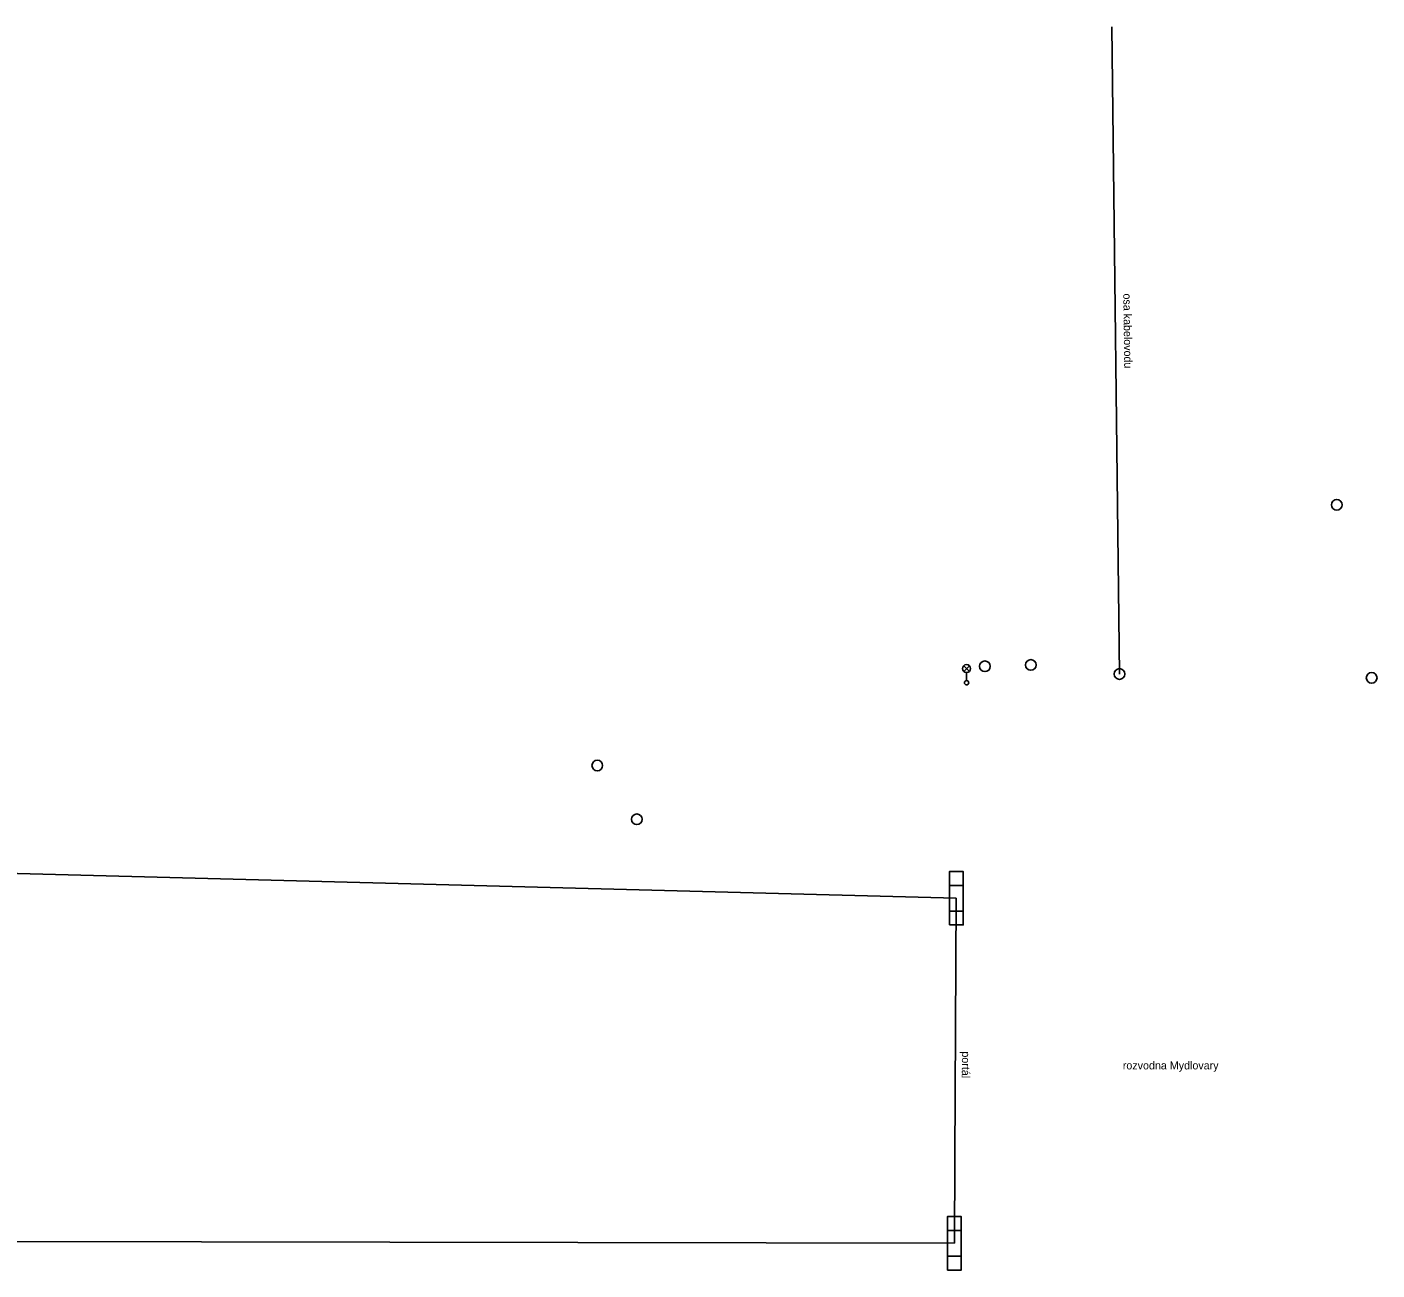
# Model space of a CAD drawing. Extents: x -763601 to -762500, y -1153000 to -1152585.
# Drawn here: x -762629.8 to -762503.3, y -1152701 to -1152584.5 of the extents above; entities that cross this region are included whole.
import ezdxf

# ---------------------------------------------------------------- set-up
doc = ezdxf.new("R2010")
doc.units = 0
for name, color, linetype in [('Vrstva 1', 7, 'Continuous'), ('Vrstva 10', 7, 'Continuous'), ('Vrstva 11', 7, 'Continuous'), ('Vrstva 2', 7, 'Continuous'), ('Vrstva 9', 7, 'Continuous')]:
    doc.layers.add(name, color=color, linetype=linetype)

msp = doc.modelspace()

# ---------------------------------------------------------------- linework, layer by layer
at = {"layer": 'Vrstva 1'}
for p, q in [((-762543.33, -1152667.4), (-762543.33, -1152665)), ((-762542.03, -1152667.4), (-762542.03, -1152665)), ((-762543.51, -1152699.74), (-762543.51, -1152697.34)), ((-762542.21, -1152699.74), (-762542.21, -1152697.34))]:
    msp.add_line(p, q, dxfattribs=at)
for points in [[(-762820.27, -1152623.02), (-762631.83, -1152663.84), (-762542.68, -1152666.2)], [(-762542.86, -1152698.54), (-762542.83, -1152690.55), (-762542.68, -1152666.2)], [(-762631.06, -1152698.36), (-762542.86, -1152698.54)]]:
    msp.add_lwpolyline(points, dxfattribs=at)
for points in [[(-762543.33, -1152665), (-762542.03, -1152665), (-762542.03, -1152663.7), (-762543.33, -1152663.7)], [(-762543.33, -1152668.7), (-762542.03, -1152668.7), (-762542.03, -1152667.4), (-762543.33, -1152667.4)], [(-762543.51, -1152697.34), (-762542.21, -1152697.34), (-762542.21, -1152696.04), (-762543.51, -1152696.04)], [(-762543.51, -1152701.04), (-762542.21, -1152701.04), (-762542.21, -1152699.74), (-762543.51, -1152699.74)]]:
    msp.add_lwpolyline(points, close=True, dxfattribs=at)
at = {"layer": 'Vrstva 11'}
msp.add_lwpolyline([(-762527.39, -1152645.18), (-762528.12, -1152584.54)], dxfattribs=at)
at = {"layer": 'Vrstva 9'}
for p, q in [((-762541.984, -1152644.938), (-762541.456, -1152644.41)), ((-762541.448, -1152644.935), (-762541.976, -1152644.406)), ((-762541.72, -1152645.05), (-762541.72, -1152645.8))]:
    msp.add_line(p, q, dxfattribs=at)
for centre, radius in [((-762507.03, -1152629.32), 0.5), ((-762541.72, -1152644.675), 0.375), ((-762540, -1152644.46), 0.5), ((-762535.7, -1152644.33), 0.5), ((-762527.39, -1152645.18), 0.5), ((-762503.76, -1152645.54), 0.5), ((-762541.72, -1152646), 0.2), ((-762576.32, -1152653.76), 0.5), ((-762572.62, -1152658.8), 0.5)]:
    msp.add_circle(centre, radius, dxfattribs=at)

# ---------------------------------------------------------------- texts
at = {"layer": 'Vrstva 10'}
msp.add_text('osa kabelovodu', height=0.75, rotation=270.68971, dxfattribs=at).set_placement((-762527.03, -1152609.52))
at = {"layer": 'Vrstva 2'}
msp.add_text('portál', height=0.75, rotation=269.6811, dxfattribs=at).set_placement((-762542.15, -1152680.55))
msp.add_text('rozvodna Mydlovary', height=0.75, dxfattribs=at).set_placement((-762527.08, -1152682.24))

doc.saveas('drawing.dxf')
